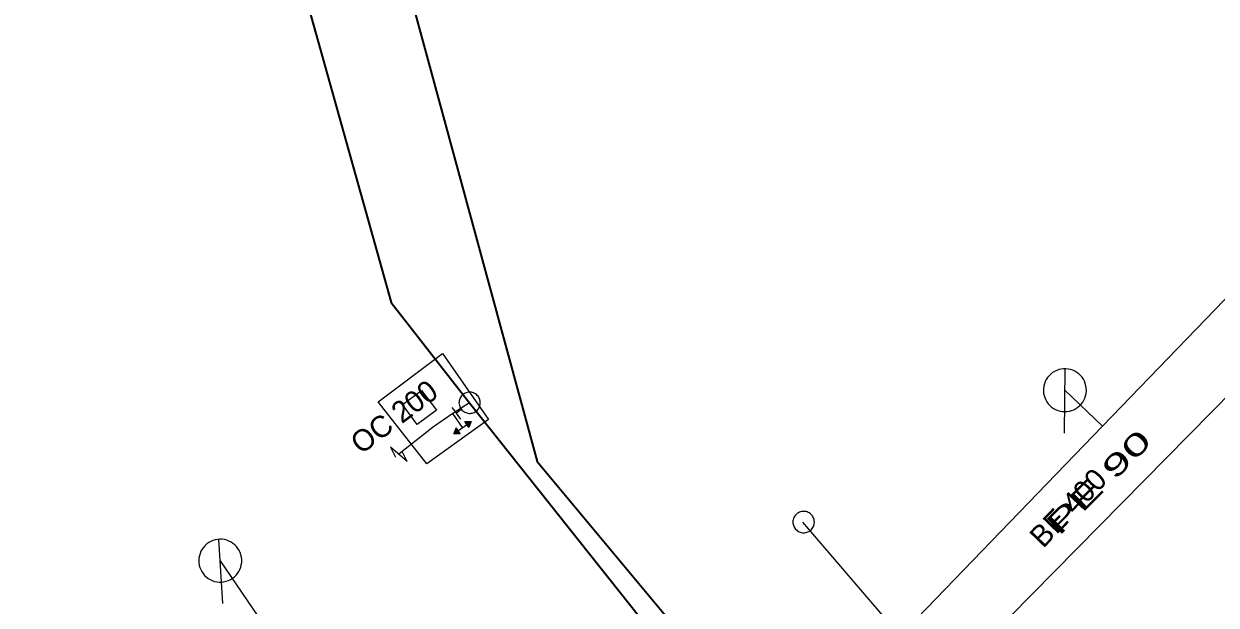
# Model space of a CAD drawing. Extents: x -779496 to -779026, y -977086 to -976624.
# Drawn here: x -779315.3 to -779259.7, y -976883.2 to -976856.2 of the extents above; entities that cross this region are included whole.
import ezdxf

# ---------------------------------------------------------------- set-up
doc = ezdxf.new("R2010")
doc.units = 0
doc.header["$LTSCALE"] = 0.4
doc.linetypes.add('MEDIUM_DASHED', pattern=[4.5, 3, -1.5])
for name, color, linetype, lineweight in [('1', 7, 'MEDIUM_DASHED', 25), ('11', 7, 'Continuous', 13), ('13', 7, 'Continuous', 13), ('14', 7, 'Continuous', 13), ('17', 7, 'Continuous', 25), ('2', 7, 'Continuous', 13), ('22', 7, 'Continuous', 13), ('23', 7, 'Continuous', 13), ('34', 7, 'Continuous', 13), ('47', 7, 'Continuous', 13)]:
    doc.layers.add(name, color=color, linetype=linetype, lineweight=lineweight)

msp = doc.modelspace()

# ---------------------------------------------------------------- linework, layer by layer
at = {"layer": '11'}
for p, q in [((-779266.788, -976873.222), (-779265.041, -976874.906)), ((-779306.139, -976881.166), (-779292.98, -976900.507))]:
    msp.add_line(p, q, dxfattribs=at)
at = {"layer": '13'}
msp.add_line((-779272.656, -976886.759), (-779278.993, -976879.365), dxfattribs=at)
at = {"layer": '14'}
msp.add_line((-779294.52, -976873.809), (-779295.309, -976874.309), dxfattribs=at)
at = {"layer": '14', "lineweight": 25}
msp.add_lwpolyline([(-779257.611, -976867.208), (-779265.041, -976874.906), (-779276.684, -976886.967)], dxfattribs=at)
at = {"layer": '17'}
for points in [[(-779276.545, -976891.073), (-779272.473, -976886.943), (-779252.653, -976866.844), (-779246.603, -976859.784), (-779242.228, -976854.603), (-779234.164, -976845.175), (-779227.585, -976837.452), (-779212.579, -976818.883), (-779210.76, -976816.627), (-779191.487, -976792.772), (-779191.372, -976792.629), (-779190.682, -976791.787), (-779189.552, -976790.451), (-779187.15, -976792.396)], [(-779295.309, -976874.309), (-779296.21, -976874.93), (-779297.82, -976876.21)]]:
    msp.add_lwpolyline(points, dxfattribs=at)
at = {"layer": '17', "lineweight": 35}
for points in [[(-779314.495, -976791.582), (-779291.37, -976876.552), (-779283.847, -976885.578)], [(-779318.746, -976795.755), (-779298.18, -976869.129), (-779294.52, -976873.809)], [(-779294.52, -976873.809), (-779286.179, -976884.319), (-779226.903, -976933.326), (-779213.28, -976944.579), (-779208.355, -976950.874)]]:
    msp.add_lwpolyline(points, dxfattribs=at)
at = {"layer": '2'}
for points in [[(-779295.779, -976871.51), (-779293.649, -976874.58), (-779296.519, -976876.65), (-779298.779, -976873.76)], [(-779297.65, -976873.884), (-779296.759, -976873.233), (-779296.066, -976874.153), (-779296.971, -976874.817)]]:
    msp.add_lwpolyline(points, close=True, dxfattribs=at)
at = {"layer": '22'}
for p, q in [((-779266.808, -976875.222), (-779266.777, -976872.222)), ((-779306.018, -976883.162), (-779306.199, -976880.168))]:
    msp.add_line(p, q, dxfattribs=at)
for points in [[(-779265.788, -976873.232), (-779265.792, -976873.123), (-779265.809, -976873.015), (-779265.838, -976872.909), (-779265.877, -976872.807), (-779265.928, -976872.71), (-779265.989, -976872.619), (-779266.061, -976872.535), (-779266.14, -976872.46), (-779266.227, -976872.394), (-779266.321, -976872.338), (-779266.42, -976872.292), (-779266.525, -976872.258), (-779266.632, -976872.235), (-779266.74, -976872.223), (-779266.85, -976872.224), (-779266.959, -976872.237), (-779267.066, -976872.261), (-779267.169, -976872.297), (-779267.268, -976872.345), (-779267.36, -976872.402), (-779267.447, -976872.47), (-779267.525, -976872.547), (-779267.595, -976872.632), (-779267.655, -976872.723), (-779267.704, -976872.821), (-779267.742, -976872.923), (-779267.769, -976873.03), (-779267.784, -976873.138), (-779267.787, -976873.248), (-779267.778, -976873.357), (-779267.758, -976873.464), (-779267.725, -976873.569), (-779267.682, -976873.669), (-779267.628, -976873.765), (-779267.563, -976873.853), (-779267.49, -976873.934), (-779267.407, -976874.007), (-779267.318, -976874.07), (-779267.223, -976874.123), (-779267.121, -976874.165), (-779267.016, -976874.196), (-779266.909, -976874.215), (-779266.799, -976874.222), (-779266.69, -976874.217), (-779266.581, -976874.2), (-779266.476, -976874.172), (-779266.374, -976874.132), (-779266.276, -976874.081), (-779266.186, -976874.02), (-779266.102, -976873.95), (-779266.026, -976873.871), (-779265.96, -976873.783), (-779265.903, -976873.69), (-779265.858, -976873.59), (-779265.823, -976873.487), (-779265.8, -976873.379), (-779265.789, -976873.27)], [(-779305.14, -976881.106), (-779305.153, -976880.997), (-779305.177, -976880.891), (-779305.214, -976880.787), (-779305.26, -976880.688), (-779305.317, -976880.595), (-779305.385, -976880.508), (-779305.462, -976880.43), (-779305.546, -976880.361), (-779305.638, -976880.3), (-779305.735, -976880.251), (-779305.837, -976880.212), (-779305.944, -976880.186), (-779306.052, -976880.17), (-779306.162, -976880.167), (-779306.271, -976880.175), (-779306.378, -976880.196), (-779306.484, -976880.227), (-779306.584, -976880.27), (-779306.679, -976880.325), (-779306.767, -976880.388), (-779306.849, -976880.463), (-779306.921, -976880.544), (-779306.985, -976880.634), (-779307.038, -976880.729), (-779307.08, -976880.83), (-779307.111, -976880.935), (-779307.131, -976881.044), (-779307.138, -976881.152), (-779307.133, -976881.262), (-779307.117, -976881.37), (-779307.09, -976881.476), (-779307.049, -976881.578), (-779306.999, -976881.675), (-779306.939, -976881.766), (-779306.868, -976881.85), (-779306.789, -976881.926), (-779306.702, -976881.992), (-779306.608, -976882.049), (-779306.509, -976882.095), (-779306.405, -976882.13), (-779306.298, -976882.153), (-779306.189, -976882.165), (-779306.079, -976882.164), (-779305.971, -976882.152), (-779305.864, -976882.127), (-779305.761, -976882.092), (-779305.662, -976882.045), (-779305.568, -976881.987), (-779305.482, -976881.92), (-779305.403, -976881.844), (-779305.333, -976881.76), (-779305.274, -976881.668), (-779305.223, -976881.571), (-779305.186, -976881.468), (-779305.158, -976881.362), (-779305.142, -976881.253), (-779305.139, -976881.144)]]:
    msp.add_lwpolyline(points, close=True, dxfattribs=at)
at = {"layer": '23'}
for p in [(-779295.352, -976874.029), (-779294.921, -976874.125), (-779294.928, -976874.566)]:
    msp.add_line(p, (-779295.14, -976874.298), dxfattribs=at)
msp.add_lwpolyline([(-779294.823, -976873.417), (-779294.864, -976873.452), (-779294.9, -976873.489), (-779294.931, -976873.532), (-779294.957, -976873.576), (-779294.98, -976873.62), (-779294.996, -976873.672), (-779295.007, -976873.722), (-779295.015, -976873.774), (-779295.017, -976873.825), (-779295.01, -976873.877), (-779295.001, -976873.928), (-779294.985, -976873.976), (-779294.965, -976874.026), (-779294.941, -976874.071), (-779294.912, -976874.113), (-779294.878, -976874.151), (-779294.839, -976874.186), (-779294.798, -976874.218), (-779294.754, -976874.245), (-779294.705, -976874.268), (-779294.658, -976874.284), (-779294.606, -976874.296), (-779294.556, -976874.302), (-779294.502, -976874.302), (-779294.451, -976874.3), (-779294.401, -976874.291), (-779294.352, -976874.275), (-779294.302, -976874.255), (-779294.259, -976874.228), (-779294.213, -976874.199), (-779294.174, -976874.165), (-779294.14, -976874.127), (-779294.107, -976874.086), (-779294.081, -976874.042), (-779294.06, -976873.995), (-779294.042, -976873.946), (-779294.032, -976873.896), (-779294.023, -976873.844), (-779294.024, -976873.79), (-779294.028, -976873.74), (-779294.039, -976873.688), (-779294.053, -976873.637), (-779294.073, -976873.592), (-779294.099, -976873.544), (-779294.129, -976873.502), (-779294.163, -976873.464), (-779294.199, -976873.428), (-779294.242, -976873.397), (-779294.286, -976873.371), (-779294.335, -976873.348), (-779294.382, -976873.332), (-779294.434, -976873.319), (-779294.485, -976873.313), (-779294.536, -976873.311), (-779294.588, -976873.318), (-779294.64, -976873.325), (-779294.689, -976873.34), (-779294.736, -976873.363), (-779294.782, -976873.387)], close=True, dxfattribs=at)
for points in [[(-779278.463, -976879.321), (-779278.469, -976879.27), (-779278.483, -976879.219), (-779278.5, -976879.17), (-779278.525, -976879.123), (-779278.552, -976879.08), (-779278.584, -976879.038), (-779278.621, -976879.001), (-779278.661, -976878.967), (-779278.705, -976878.937), (-779278.751, -976878.914), (-779278.8, -976878.894), (-779278.849, -976878.879), (-779278.902, -976878.872), (-779278.953, -976878.867), (-779279.005, -976878.87), (-779279.058, -976878.877), (-779279.109, -976878.89), (-779279.158, -976878.908), (-779279.204, -976878.932), (-779279.248, -976878.959), (-779279.29, -976878.991), (-779279.328, -976879.028), (-779279.362, -976879.068), (-779279.389, -976879.112), (-779279.414, -976879.158), (-779279.433, -976879.206), (-779279.447, -976879.258), (-779279.456, -976879.309), (-779279.459, -976879.36), (-779279.458, -976879.413), (-779279.45, -976879.464), (-779279.438, -976879.516), (-779279.419, -976879.565), (-779279.396, -976879.612), (-779279.368, -976879.655), (-779279.337, -976879.696), (-779279.299, -976879.735), (-779279.26, -976879.768), (-779279.215, -976879.797)], [(-779279.158, -976878.908), (-779279.204, -976878.932), (-779279.248, -976878.959), (-779279.29, -976878.991)], [(-779279.215, -976879.797), (-779279.171, -976879.821), (-779279.122, -976879.841), (-779279.07, -976879.855), (-779279.018, -976879.864), (-779278.966, -976879.867), (-779278.914, -976879.866), (-779278.863, -976879.858), (-779278.811, -976879.844), (-779278.763, -976879.826), (-779278.716, -976879.803), (-779278.672, -976879.775), (-779278.631, -976879.743), (-779278.593, -976879.707), (-779278.559, -976879.666), (-779278.53, -976879.622), (-779278.506, -976879.577), (-779278.488, -976879.529), (-779278.473, -976879.478), (-779278.464, -976879.426), (-779278.46, -976879.373), (-779278.463, -976879.321), (-779278.469, -976879.27), (-779278.483, -976879.219), (-779278.5, -976879.17), (-779278.525, -976879.123), (-779278.552, -976879.08), (-779278.584, -976879.038), (-779278.621, -976879.001), (-779278.661, -976878.967), (-779278.705, -976878.937), (-779278.751, -976878.914), (-779278.8, -976878.894), (-779278.849, -976878.879), (-779278.902, -976878.872), (-779278.953, -976878.867), (-779279.005, -976878.87), (-779279.058, -976878.877), (-779279.109, -976878.89), (-779279.158, -976878.908)], [(-779279.29, -976878.991), (-779279.328, -976879.028), (-779279.362, -976879.068), (-779279.389, -976879.112), (-779279.414, -976879.158), (-779279.433, -976879.206), (-779279.447, -976879.258), (-779279.456, -976879.309), (-779279.459, -976879.36), (-779279.458, -976879.413), (-779279.45, -976879.464), (-779279.438, -976879.516), (-779279.419, -976879.565), (-779279.396, -976879.612), (-779279.368, -976879.655), (-779279.337, -976879.696), (-779279.299, -976879.735), (-779279.26, -976879.768), (-779279.215, -976879.797), (-779279.171, -976879.821), (-779279.122, -976879.841), (-779279.07, -976879.855), (-779279.018, -976879.864), (-779278.966, -976879.867), (-779278.914, -976879.866), (-779278.863, -976879.858), (-779278.811, -976879.844), (-779278.763, -976879.826), (-779278.716, -976879.803), (-779278.672, -976879.775), (-779278.631, -976879.743), (-779278.593, -976879.707), (-779278.559, -976879.666), (-779278.53, -976879.622), (-779278.506, -976879.577), (-779278.488, -976879.529), (-779278.473, -976879.478), (-779278.464, -976879.426), (-779278.46, -976879.373), (-779278.463, -976879.321)]]:
    msp.add_lwpolyline(points, dxfattribs=at)
at = {"layer": '34'}
for p, q in [((-779294.854, -976874.968), (-779295.308, -976874.309)), ((-779295.055, -976875.242), (-779295.187, -976875.056)), ((-779295.024, -976875.245), (-779295.179, -976875.026)), ((-779294.993, -976875.242), (-779295.165, -976874.997)), ((-779294.744, -976874.688), (-779294.446, -976874.686)), ((-779294.549, -976874.936), (-779294.716, -976874.688)), ((-779294.535, -976874.908), (-779294.684, -976874.686)), ((-779294.526, -976874.878), (-779294.653, -976874.688)), ((-779294.514, -976874.851), (-779294.625, -976874.688)), ((-779294.505, -976874.825), (-779294.597, -976874.687)), ((-779294.49, -976874.797), (-779294.565, -976874.686)), ((-779294.48, -976874.771), (-779294.537, -976874.686)), ((-779294.471, -976874.741), (-779294.506, -976874.689)), ((-779294.456, -976874.713), (-779294.474, -976874.686)), ((-779295.235, -976875.249), (-779295.253, -976875.223)), ((-779295.202, -976875.245), (-779295.239, -976875.194)), ((-779295.172, -976875.247), (-779295.231, -976875.164)), ((-779295.144, -976875.247), (-779295.221, -976875.138)), ((-779295.112, -976875.244), (-779295.208, -976875.108)), ((-779295.084, -976875.244), (-779295.198, -976875.083))]:
    msp.add_line(p, q, dxfattribs=at)
for points in [[(-779295.156, -976874.971), (-779295.263, -976875.249), (-779294.446, -976874.686)], [(-779295.263, -976875.249), (-779294.964, -976875.242), (-779295.156, -976874.971)], [(-779294.446, -976874.686), (-779294.559, -976874.962), (-779294.744, -976874.688)]]:
    msp.add_lwpolyline(points, dxfattribs=at)
at = {"layer": '47'}
msp.add_line((-779297.432, -976876.54), (-779297.662, -976876.084), dxfattribs=at)
msp.add_lwpolyline([(-779297.432, -976876.54), (-779298.207, -976875.879), (-779297.977, -976876.335)], dxfattribs=at)

# ---------------------------------------------------------------- texts
at = {"layer": '1'}
for s, rotation, p in [('OC 200', 37, (-779299.581, -976876.245)), ('BE 400', 46, (-779267.802, -976880.624))]:
    msp.add_text(s, height=1, rotation=rotation, dxfattribs=at).set_placement(p)
at = {"layer": '1', "width": 1.7}
msp.add_text('PE 90 ', height=1, rotation=45, dxfattribs=at).set_placement((-779267.055, -976880.046))

doc.saveas('drawing.dxf')
